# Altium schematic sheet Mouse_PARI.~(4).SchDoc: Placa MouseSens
size A4; PageSetup: Record=PageOptions|CenterHorizontal=True|CenterVertical=True|PrintScale=1.00|XCorrection=1.00|YCorrection=1.00|PrintKind=0|BorderSize=5000000|LeftOffset=0|BottomOffset=0|Orientation=2|PaperLength=1000|PaperWidth=1000|Scale=100|PaperSource=15|PrintQuality=1200|MediaType=1|DitherType=10|PaperKind=A4|PrintScaleMode=0
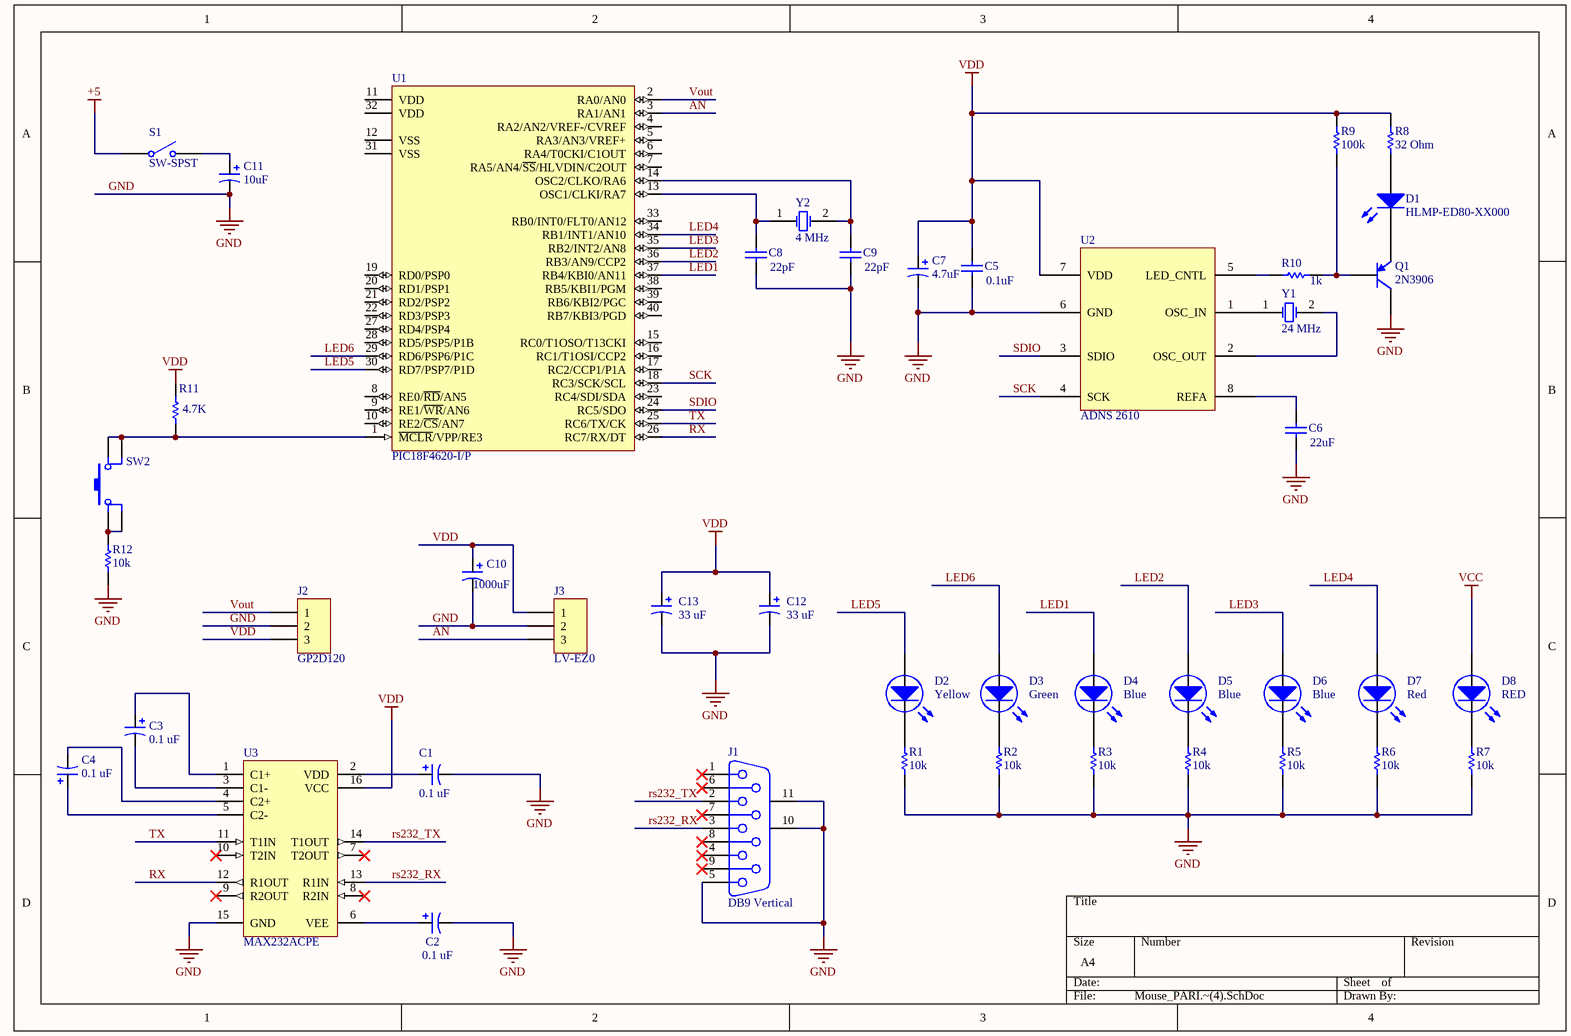
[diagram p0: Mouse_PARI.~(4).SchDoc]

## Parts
C1  0.1 uF  [KEMET C410C104M5U5CA-TR]
C2  0.1 uF  [KEMET C410C104M5U5CA-TR]
C3  0.1 uF  [KEMET C410C104M5U5CA-TR]
C4  0.1 uF  [KEMET C410C104M5U5CA-TR]
C5  value 0.1uF  [RAD-0.3]  (hidden comment: Cap)
C6  value 22uF  [RAD-0.3]  (hidden comment: Cap)
C7  4.7uF  [KEMET C410C104M5U5CA-TR]
C8  value 22pF  [RAD-0.3]  (hidden comment: Cap)
C9  value 22pF  [RAD-0.3]  (hidden comment: Cap)
C10  1000uF  [KEMET C410C104M5U5CA-TR]
C11  10uF  [KEMET C410C104M5U5CA-TR]
C12  33 uF  [PANASONIC ECEA0JKS330]
C13  33 uF  [PANASONIC ECEA0JKS330]
D1  HLMP-ED80-XX000  [2.2X2.1X2.9]
D2  Yellow  [VISHAY TLLR4401]
D3  Green  [VISHAY TLLR4401]
D4  Blue  [VISHAY TLLR4401]
D5  Blue  [VISHAY TLLR4401]
D6  Blue  [VISHAY TLLR4401]
D7  Red  [VISHAY TLLR4401]
D8  RED  [VISHAY TLLR4401]
J1  DB9 Vertical  [TYCO 2-106505-2]
J2  GP2D120  [SAMTEC TSW-103-XX-X-S]
J3  LV-EZ0  [SAMTEC TSW-103-XX-X-S]
Q1  2N3906  [TO-92A]
R1  10k  [Resistência]
R2  10k  [Resistência]
R3  10k  [Resistência]
R4  10k  [Resistência]
R5  10k  [Resistência]
R6  10k  [Resistência]
R7  10k  [Resistência]
R8  32 Ohm  [Resistência]
R9  100k  [Resistência]
R10  1k  [Resistência]
R11  4.7K  [TYCO 1-1625875-2]
R12  10k  [Resistência]
S1  SW-SPST  [SPST-2]
SW2  OMRON B3F-1002  [OMRON B3F-1002]  (value not drawn)
U1  PIC18F4620-I/P  [PDIP600-P40]
U2  ADNS 2610
U3  MAX232ACPE  [PE16A]
Y1  24 MHz  [R38]
Y2  4 MHz  [R38]

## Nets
+5: S1.1(COMMON)
GND: C1.2 C2.2 C5.1 C6.1 C7.2 C8.1 C9.1 C10.2 C11.2 C12.2 C13.2 J1.5 J1.10(MH1) J1.11(MH2) J2.2 J3.2 Q1.3(C) R1.2 R2.2 R3.2 R4.2 R5.2 R6.2 R7.2 R12.2 U2.6(GND) U3.15(GND)
VCC: D8.1(A)
VDD: C5.2 C7.1 C10.1 C12.1 C13.1 J2.3 J3.1 R8.1 R9.1 R11.2 U2.7(VDD) U3.16(VCC)
AN: J3.3 U1.3(RA1/AN1)
LED1: D4.1(A) U1.37(RB4/KBI0/AN11)
LED2: D5.1(A) U1.36(RB3/AN9/CCP2)
LED3: D6.1(A) U1.35(RB2/INT2/AN8)
LED4: D7.1(A) U1.34(RB1/INT1/AN10)
LED5: D2.1(A) U1.30(RD7/PSP7/P1D)
LED6: D3.1(A) U1.29(RD6/PSP6/P1C)
rs232_RX: J1.3 U3.13(R1IN)
rs232_TX: J1.2 U3.14(T1OUT)
RX: U1.26(RC7/RX/DT) U3.12(R1OUT)
SCK: U1.18(RC3/SCK/SCL) U2.4(SCK)
SDIO: U1.24(RC5/SDO) U2.3(SDIO)
TX: U1.25(RC6/TX/CK) U3.11(T1IN)
Vout: J2.1 U1.2(RA0/AN0)
NetC1_1: C1.1 U3.2(VDD)
NetC2_1: C2.1 U3.6(VEE)
NetC3_1: C3.1 U3.1(C1+)
NetC3_2: C3.2 U3.3(C1-)
NetC4_1: C4.1 U3.5(C2-)
NetC4_2: C4.2 U3.4(C2+)
NetC6_2: C6.2 U2.8(REFA)
NetC8_2: C8.2 U1.13(OSC1/CLKI/RA7) Y2.1(OSC1)
NetC9_2: C9.2 U1.14(OSC2/CLKO/RA6) Y2.2(OSC2)
NetC11_1: C11.1 S1.2(NO)
NetD1_1: D1.1(A) R8.2
NetD1_2: D1.2(K) Q1.1(E)
NetD2_2: D2.2(K) R1.1
NetD3_2: D3.2(K) R2.1
NetD4_2: D4.2(K) R3.1
NetD5_2: D5.2(K) R4.1
NetD6_2: D6.2(K) R5.1
NetD7_2: D7.2(K) R6.1
NetD8_2: D8.2(K) R7.1
NetQ1_2: Q1.2(B) R9.2 R10.2
NetR10_1: R10.1 U2.5(LED_CNTL)
NetR11_1: R11.1 SW2.1 SW2.2 U1.1(~{MCLR}/VPP/RE3)
NetR12_1: R12.1 SW2.3 SW2.4
NetU2_1: U2.1(OSC_IN) Y1.1(OSC1)
NetU2_2: U2.2(OSC_OUT) Y1.2(OSC2)

Not connected (* = marked no-connect by the designer): J1 1* 4* 6* 7* 8* 9*; U1 4(RA2/AN2/VREF-/CVREF) 5(RA3/AN3/VREF+) 6(RA4/T0CKI/C1OUT) 7(RA5/AN4/~{SS}/HLVDIN/C2OUT) 8(RE0/~{RD}/AN5) 9(RE1/~{WR}/AN6) 10(RE2/~{CS}/AN7) 11(VDD) 12(VSS) 15(RC0/T1OSO/T13CKI) 16(RC1/T1OSI/CCP2) 17(RC2/CCP1/P1A) 19(RD0/PSP0) 20(RD1/PSP1) 21(RD2/PSP2) 22(RD3/PSP3) 23(RC4/SDI/SDA) 27(RD4/PSP4) 28(RD5/PSP5/P1B) 31(VSS) 32(VDD) 33(RB0/INT0/FLT0/AN12) 38(RB5/KBI1/PGM) 39(RB6/KBI2/PGC) 40(RB7/KBI3/PGD); U3 7(T2OUT)* 8(R2IN)* 9(R2OUT)* 10(T2IN)*

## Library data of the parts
C1-C4 C7 C10 C11 = KEMET C410C104M5U5CA-TR: 0.1 uF axial capacitor 50V Z5U
C5 C6 C8 C9 = Cap: Capacitor
C12 C13 = PANASONIC ECEA0JKS330: 33 uF radial aluminium electrolytic Capacitor 6.3V
D1 = HLMP-6300-F0011: Subminiature Red LED Lamp; LuminousIntensity: 1mcd (Minimum).; PCB_Layout: Complies with manufacturer's recommendation.
D2-D8 = VISHAY TLLG4401: Green LED PCB 3mm
J1 = TYCO 2-106505-2
J2 J3 = SAMTEC TSW-103-07-G-S: 3 pin 2.54mm pitch header
Q1 = 2N3906: PNP General Purpose Amplifier
R1-R10 R12 = Resistência
R11 = TYCO 1-1625875-2: 1k Ohm 1/4 W 5%
S1 = SW-SPST: Single-Pole, Single-Throw Switch
SW2 = OMRON B3F-1002: 6.0mm Tact Switch
U1 = PIC18F4620-I/P: Enhanced Flash Microcontroller with 10-Bit A/D and nanoWatt Technology, 64K Flash, 40-Pin PDIP, Industrial Temperature Range
U2 = ADNS-2610
U3 = MAX232ACPE: +5V Powered, Multi-Channel RS-232 Driver/Receiver
Y1 Y2 = XTAL: Crystal Oscillator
